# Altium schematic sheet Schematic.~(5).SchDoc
size A4; SheetNumber: 1; SheetTotal: 1
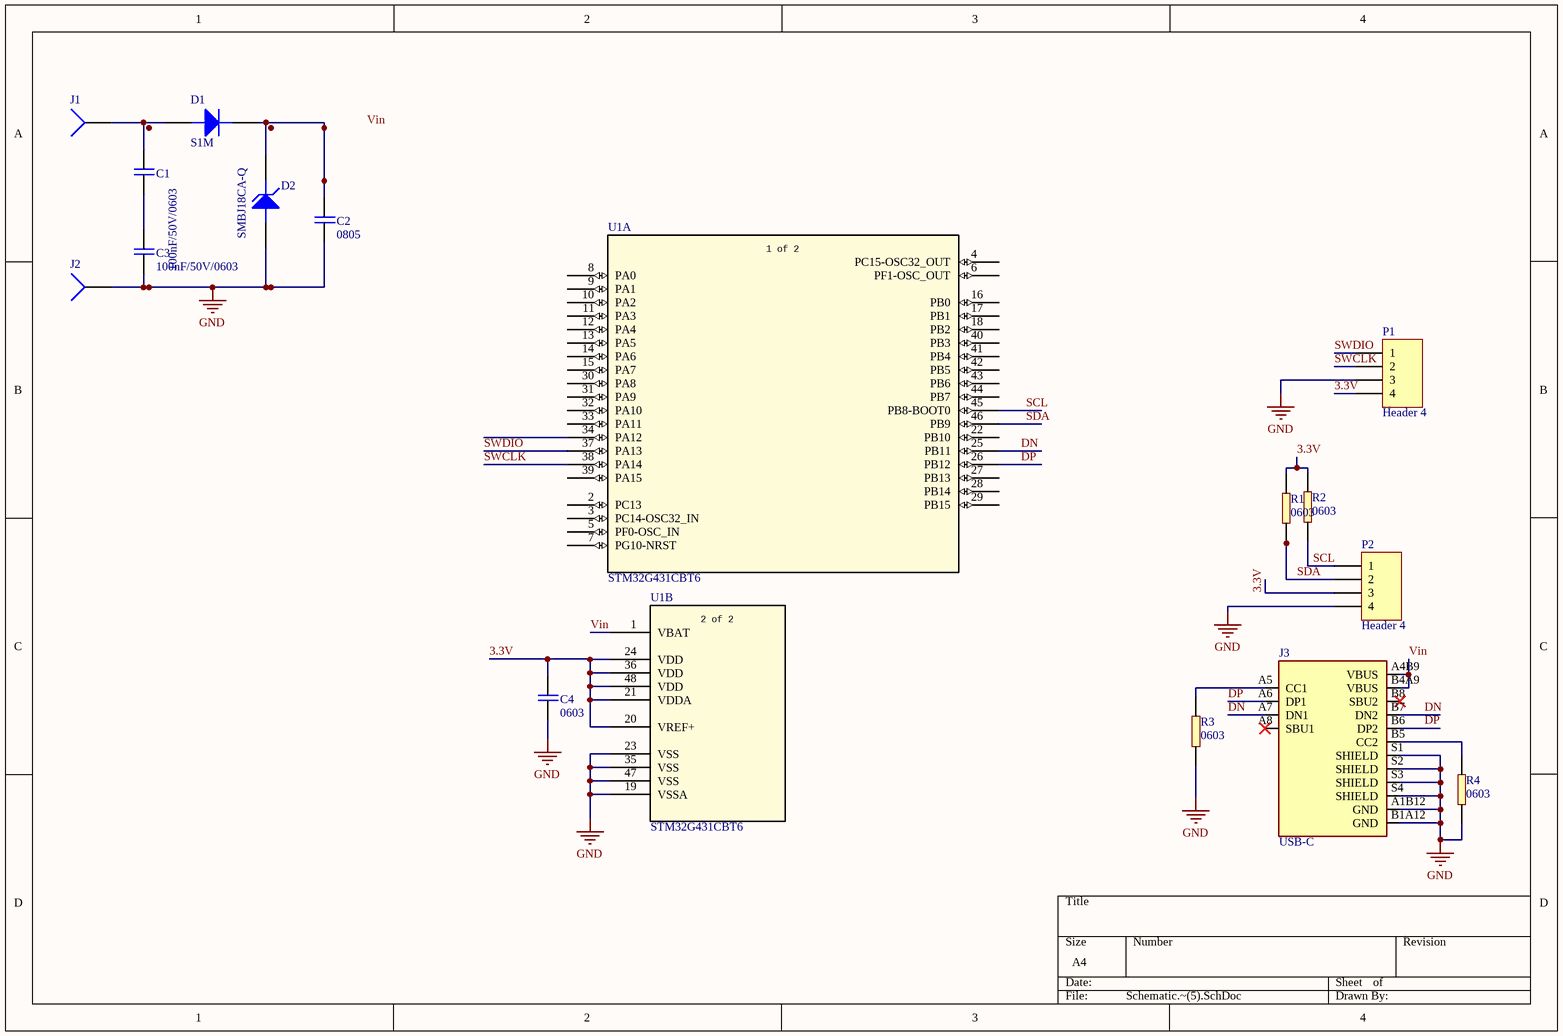
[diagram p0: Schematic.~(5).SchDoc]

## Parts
C1  100nF/50V/0603  [C0603]
C2  0805  [C0805]
C3  100nF/50V/0603  [C0603]
C4  0603  [C0603]
D1  S1M  [S1M]
D2  SMBJ18CA-Q  [SMBJ18CA-Q]
J1  Socket  [PIN1]  (value not drawn)
J2  Socket  [PIN1]  (value not drawn)
J3  USB-C  [HRO_TYPE-C-31-M-12]
P1  Header 4  [HDR1X4]
P2  Header 4  [HDR1X4]
R1  0603  [R0603]
R2  0603  [R0603]
R3  0603  [R0603]
R4  0603  [R0603]
U1  STM32G431CBT6  [LQFP48-7x7mm]  (parts A,B of 2)

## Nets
GND: C2.1 C3.1 C4.1 D2.A J2.1 J3.A1B12(GND) J3.B1A12(GND) J3.S1(SHIELD) J3.S2(SHIELD) J3.S3(SHIELD) J3.S4(SHIELD) P1.3 P2.4 R3.1 R4.1 U1.19(VSSA) U1.23(VSS) U1.35(VSS) U1.47(VSS)
3.3V: C4.2 P1.4 P2.3 R1.2 R2.2 U1.20(VREF+) U1.21(VDDA) U1.24(VDD) U1.36(VDD) U1.48(VDD)
DN: J3.A7(DN1) J3.B7(DN2) U1.25(PB11)
DP: J3.A6(DP1) J3.B6(DP2) U1.26(PB12)
SCL: P2.1 R2.1 U1.45(PB8-BOOT0)
SDA: P2.2 R1.1 U1.46(PB9)
SWCLK: P1.2 U1.38(PA14)
SWDIO: P1.1 U1.37(PA13)
Vin: J3.A4B9(VBUS) J3.B4A9(VBUS) U1.1(VBAT)
NetC1_1: C1.1 C3.2
NetC1_2: C1.2 D1.A J1.1
NetC2_2: C2.2 D1.K D2.K
NetJ3_A5: J3.A5(CC1) R3.2
NetJ3_B5: J3.B5(CC2) R4.2

Not connected (* = marked no-connect by the designer): J3 A8(SBU1)* B8(SBU2)*; U1 2(PC13) 3(PC14-OSC32_IN) 4(PC15-OSC32_OUT) 5(PF0-OSC_IN) 6(PF1-OSC_OUT) 7(PG10-NRST) 8(PA0) 9(PA1) 10(PA2) 11(PA3) 12(PA4) 13(PA5) 14(PA6) 15(PA7) 16(PB0) 17(PB1) 18(PB2) 22(PB10) 27(PB13) 28(PB14) 29(PB15) 30(PA8) 31(PA9) 32(PA10) 33(PA11) 34(PA12) 39(PA15) 40(PB3) 41(PB4) 42(PB5) 43(PB6) 44(PB7)

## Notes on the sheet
- Labels drawn without touching a wire or pin: Vin

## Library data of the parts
C1 C3 C4 = C0603
C2 = C0805
D1 = S1M: VR=1000V IF=1A 6.6pF Trr=1.8us P=1.4W; Manufacturer: ON Semiconductor / Fairchild; Max Reverse Current: 1uA; Recovery Time: 1800ns; Forward Voltage: 1V; Forward Current: 1A; Reverse Recovery Time: 1.8us; Max Repetitive Reverse Voltage (Vrrm): 1kV; Peak Non-Repetitive Surge Current: 30A; Max Surge Current: 40A; Element Configuration: Single; Polarity: Standard; Capacitance: 12pF; Power Dissipation: 1.4W
J3 = USB-C: USB-C (USB TYPE-C) USB 3.2 Gen 2 (USB 3.1 Gen 2, Superspeed + (USB 3.1)) Receptacle Connector 24 Position Surface Mount, Through Hole; MF: Adam Technologies
P1 P2 = Header 4: Header, 4-Pin
R1-R4 = R0603
U1 = STM32G431CBT6: Mainstream Arm Cortex-M4 MCU 170 MHz with 128 Kbytes of Flash memory, Math Accelerator, Medium Analog level integration; Manufacturer_Name: STMicroelectronics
